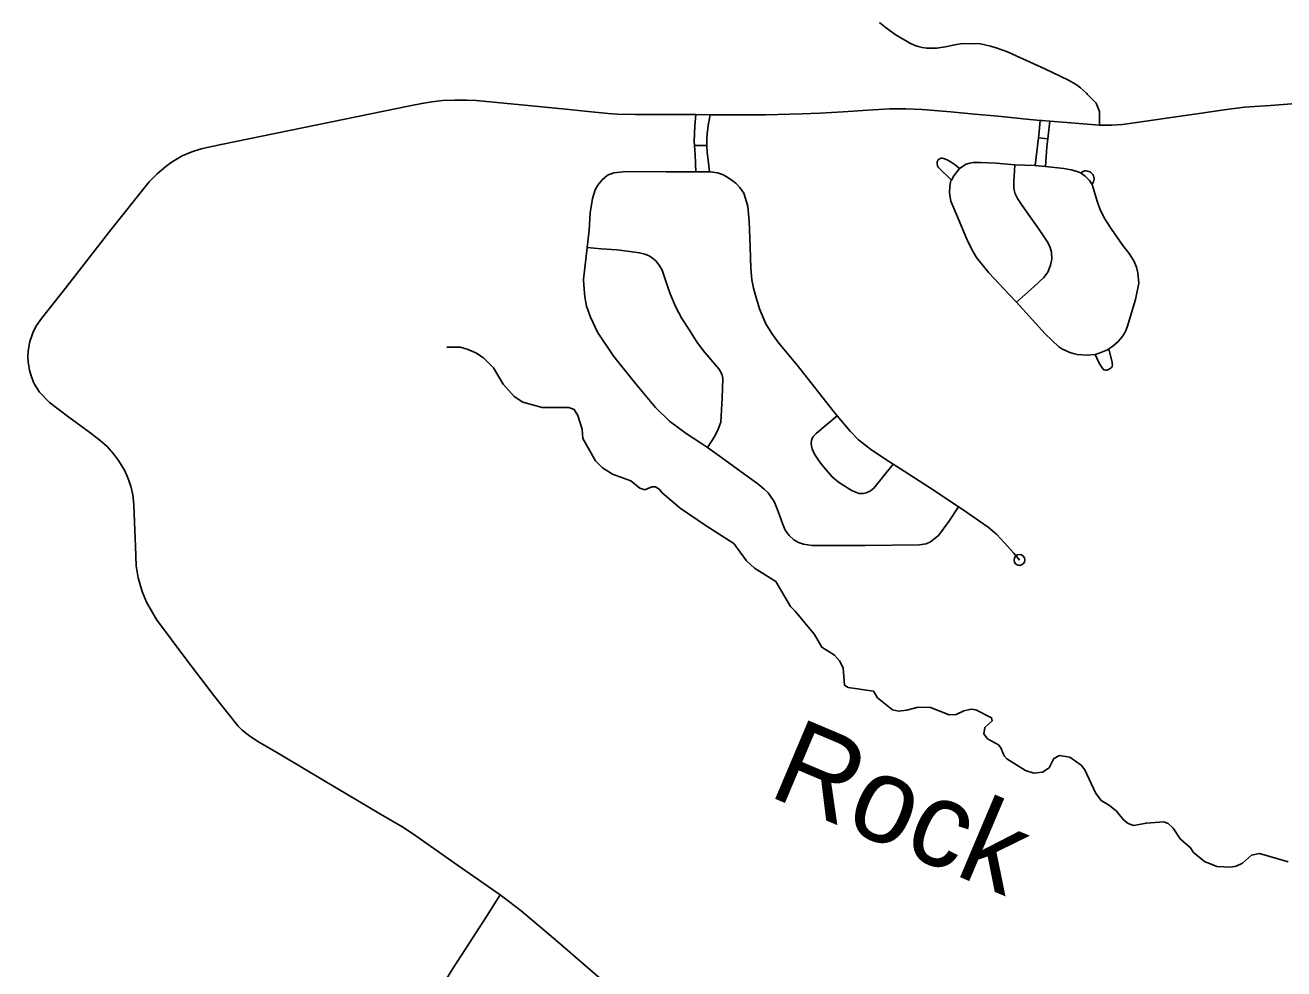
# Model space of a CAD drawing. Extents: x -19 to 366, y -4 to 359.
# Drawn here: x 142.275 to 143.458, y 193.183 to 194.069 of the extents above; entities that cross this region are included whole.
import ezdxf

# ---------------------------------------------------------------- set-up
doc = ezdxf.new("R2010")
doc.units = 0
for name, color, linetype in [('R_ROW Annot', 7, 'Continuous'), ('R_Striping', 7, 'Continuous'), ('R_Survey Control', 7, 'Continuous'), ('R_Temp Easement', 7, 'Continuous'), ('Sheet Fence', 7, 'Continuous')]:
    doc.layers.add(name, color=color, linetype=linetype)

msp = doc.modelspace()

# ---------------------------------------------------------------- linework, layer by layer
at = {"layer": 'R_ROW Annot'}
msp.add_lwpolyline([(143.2733, 194.0043), (143.2725, 194.0053), (143.2699, 194.008), (143.2671, 194.0104), (143.2642, 194.0126), (143.2624, 194.0137), (143.2556, 194.0177), (143.2336, 194.0281), (143.2162, 194.0361), (143.2066, 194.0405), (143.1985, 194.0441), (143.1932, 194.0462), (143.1879, 194.048), (143.1825, 194.0496), (143.177, 194.0508), (143.173, 194.0516), (143.1569, 194.052), (143.1541, 194.0516), (143.1506, 194.0511), (143.1473, 194.0505), (143.1445, 194.0499), (143.1418, 194.0493), (143.1319, 194.0477), (143.1279, 194.0475), (143.1228, 194.0475), (143.1181, 194.0483), (143.1145, 194.0491), (143.1115, 194.0501), (143.1067, 194.0524), (143.104, 194.0539), (143.0959, 194.0585), (143.0929, 194.0604), (143.0857, 194.0658), (143.0834, 194.0675), (143.0782, 194.0717)], dxfattribs=at)
at = {"layer": 'R_Striping'}
for p, q in [((142.9043, 193.9562), (142.9159, 193.9562)), ((143.2276, 193.9633), (143.2364, 193.9625)), ((142.8034, 193.8604), (142.8052, 193.8768)), ((142.8001, 193.8303), (142.8034, 193.8604)), ((143.0189, 193.686), (143.0385, 193.7023)), ((143.0727, 193.6344), (143.091, 193.657))]:
    msp.add_line(p, q, dxfattribs=at)
for points in [[(143.2848, 193.9752), (143.2962, 193.9752), (143.3065, 193.976), (143.3764, 193.9858), (143.4042, 193.99), (143.4212, 193.9921), (143.4455, 193.9938), (143.4694, 193.9957), (143.4884, 193.9971), (143.5084, 193.9987), (143.5217, 194.0017), (143.5469, 194.0079), (143.5711, 194.0132), (143.5843, 194.0154), (143.5968, 194.0164), (143.608, 194.0172), (143.6204, 194.0177), (143.6361, 194.0167), (143.6637, 194.0127), (143.6699, 194.0116)], [(142.8853, 193.9853), (142.8485, 193.9854), (142.8319, 193.9855), (142.8233, 193.9862), (142.8012, 193.9885), (142.7835, 193.9903), (142.7414, 193.9943), (142.6992, 193.9984), (142.6904, 193.9987), (142.6789, 193.9988), (142.6674, 193.9985), (142.6576, 193.9973), (142.648, 193.9957), (142.6368, 193.9933), (142.5498, 193.9755), (142.4595, 193.9572), (142.4406, 193.9532), (142.4319, 193.9503), (142.4229, 193.9464), (142.4136, 193.941), (142.4074, 193.9364), (142.3993, 193.9295), (142.3919, 193.9221), (142.3559, 193.8769), (142.3133, 193.8223), (142.2906, 193.7937), (142.286, 193.7872), (142.2829, 193.7812), (142.2816, 193.7773), (142.2797, 193.772), (142.2787, 193.7672), (142.2782, 193.7626), (142.278, 193.758), (142.2782, 193.7529), (142.2788, 193.749), (142.2795, 193.7453), (142.2811, 193.7397), (142.2836, 193.7329), (142.2888, 193.7246), (142.2981, 193.7148), (142.3163, 193.7011), (142.3361, 193.6865), (142.3459, 193.6792), (142.3524, 193.6733), (142.3584, 193.6667), (142.3631, 193.6604), (142.3686, 193.6513), (142.3719, 193.6441), (142.3746, 193.6362), (142.3766, 193.6281), (142.3774, 193.6191), (142.378, 193.6025), (142.3792, 193.5799), (142.3797, 193.5612), (142.3814, 193.5502), (142.3853, 193.5371), (142.3893, 193.5271), (142.3987, 193.511), (142.4273, 193.4728), (142.4537, 193.4383), (142.4756, 193.4106), (142.4793, 193.407), (142.4865, 193.4013), (142.4945, 193.3961), (142.5156, 193.3838), (142.5575, 193.3588), (142.6092, 193.3282), (142.6309, 193.3154), (142.6423, 193.3076), (142.6817, 193.2803), (142.7216, 193.2522)], [(143.1895, 193.9838), (143.1674, 193.9857), (143.145, 193.9878), (143.1181, 193.9901), (143.103, 193.9907), (143.0878, 193.9905), (143.0671, 193.9895), (143.0439, 193.9878), (143.0222, 193.9867), (143.0055, 193.9858), (142.9711, 193.9849), (142.919, 193.9851)], [(142.9054, 193.9852), (142.8853, 193.9853)], [(142.9043, 193.9562), (142.9041, 193.9601), (142.9046, 193.9746), (142.9054, 193.9852)], [(142.919, 193.9851), (142.9054, 193.9852)], [(142.919, 193.9851), (142.9171, 193.975), (142.9162, 193.9671), (142.916, 193.9621), (142.9159, 193.9562)], [(143.229, 193.9798), (143.2132, 193.9814), (143.1895, 193.9838)], [(143.229, 193.9798), (143.2279, 193.966), (143.2276, 193.9633)], [(143.2381, 193.9791), (143.2311, 193.9796), (143.229, 193.9798)], [(143.2381, 193.9791), (143.2367, 193.9653), (143.2364, 193.9625)], [(143.2849, 193.9752), (143.2542, 193.9778), (143.2381, 193.9791)], [(142.9056, 193.9314), (142.9048, 193.9473), (142.9043, 193.9562)], [(142.9159, 193.9562), (142.9159, 193.9562), (142.9162, 193.95), (142.9179, 193.937), (142.9184, 193.9314)], [(143.2276, 193.9633), (143.2244, 193.9373)], [(143.2364, 193.9625), (143.2355, 193.955), (143.2341, 193.9366)], [(143.1457, 193.9237), (143.1334, 193.9357), (143.1326, 193.9371), (143.1322, 193.9389), (143.1323, 193.9408), (143.1334, 193.9427), (143.1343, 193.9434), (143.1352, 193.944), (143.1361, 193.9442), (143.1371, 193.9442), (143.1391, 193.9437), (143.1418, 193.9428), (143.1456, 193.9405), (143.1493, 193.938), (143.1534, 193.9346)], [(142.8052, 193.8768), (142.8064, 193.8928), (142.8083, 193.9065), (142.811, 193.9145), (142.8135, 193.9188), (142.8174, 193.9238), (142.8227, 193.9282), (142.8285, 193.9305), (142.8373, 193.9314), (142.8542, 193.9319), (142.8777, 193.9314), (142.9056, 193.9314)], [(142.9056, 193.9314), (142.9184, 193.9314)], [(142.9184, 193.9314), (142.9193, 193.9314), (142.9258, 193.9306), (142.9305, 193.9291), (142.9341, 193.9272), (142.9385, 193.9244), (142.9431, 193.9209), (142.947, 193.9168), (142.9505, 193.9113), (142.9532, 193.9033), (142.9545, 193.899), (142.9557, 193.885), (142.9565, 193.8608), (142.9573, 193.8409), (142.9582, 193.83), (142.9597, 193.8223), (142.9618, 193.8143), (142.9653, 193.8027), (142.9713, 193.7887), (142.9769, 193.7795), (142.9836, 193.7706), (143.0012, 193.7496), (143.0343, 193.7074), (143.0385, 193.7023)], [(143.1457, 193.9237), (143.1481, 193.9278), (143.1532, 193.9345), (143.1534, 193.9346)], [(143.1534, 193.9346), (143.1596, 193.9386), (143.1631, 193.9396), (143.1662, 193.9402), (143.1732, 193.9403), (143.1878, 193.9395)], [(143.1878, 193.9395), (143.2054, 193.9381)], [(143.2068, 193.8089), (143.2234, 193.8236), (143.2326, 193.8322), (143.2364, 193.8373), (143.2389, 193.8437), (143.2399, 193.8495), (143.2396, 193.856), (143.2385, 193.8605), (143.2362, 193.8652), (143.2287, 193.8762), (143.2122, 193.8997), (143.2078, 193.9063), (143.2056, 193.9107), (143.2047, 193.9146), (143.2045, 193.9168), (143.2044, 193.922), (143.2054, 193.9381)], [(143.2054, 193.9381), (143.2241, 193.9373), (143.2244, 193.9373)], [(143.2244, 193.9373), (143.2341, 193.9366)], [(143.2341, 193.9366), (143.2514, 193.9345), (143.2581, 193.9333), (143.2639, 193.9317), (143.2669, 193.9304)], [(143.1504, 193.8913), (143.1453, 193.9039), (143.1446, 193.9077), (143.144, 193.912), (143.1442, 193.9181), (143.1453, 193.9232), (143.1457, 193.9237)], [(143.2669, 193.9304), (143.268, 193.9299), (143.2714, 193.9275), (143.2753, 193.9234), (143.2778, 193.9197), (143.2778, 193.9196)], [(143.2778, 193.9196), (143.2799, 193.9132), (143.2826, 193.9039), (143.2855, 193.8957), (143.2899, 193.8872), (143.2914, 193.8847)], [(143.2068, 193.8089), (143.2004, 193.8159), (143.1808, 193.8365), (143.1693, 193.8509), (143.165, 193.8585), (143.1601, 193.8683), (143.1504, 193.8913)], [(143.3219, 193.827), (143.321, 193.8366), (143.3196, 193.8418), (143.317, 193.8478), (143.3127, 193.8546), (143.3069, 193.8624), (143.2961, 193.8777), (143.2914, 193.8847)], [(142.9164, 193.6725), (142.9233, 193.6833), (142.9266, 193.6896), (142.9289, 193.6962), (142.9303, 193.7191), (142.931, 193.7372), (142.9304, 193.7405), (142.9291, 193.7434), (142.9271, 193.7463), (142.914, 193.7617), (142.9068, 193.7711), (142.8995, 193.7827), (142.8924, 193.7938), (142.8867, 193.8044), (142.8815, 193.8168), (142.8789, 193.8241), (142.8765, 193.8315), (142.8739, 193.8391), (142.871, 193.8439), (142.8679, 193.8479), (142.8649, 193.8505), (142.8618, 193.8526), (142.8577, 193.8542), (142.8526, 193.8553), (142.8436, 193.8567), (142.8312, 193.8581), (142.8166, 193.8592), (142.8034, 193.8604)], [(142.8001, 193.8303), (142.8003, 193.8249), (142.8012, 193.8139), (142.8029, 193.8053), (142.8066, 193.7948), (142.8133, 193.7807), (142.8284, 193.7581), (142.8489, 193.7327), (142.8675, 193.7101), (142.8808, 193.6972), (142.8966, 193.6855), (142.911, 193.6763), (142.9164, 193.6725)], [(143.3219, 193.827), (143.3187, 193.8115), (143.3108, 193.7854), (143.309, 193.7809), (143.3061, 193.7766), (143.3024, 193.7722), (143.2975, 193.7677), (143.2936, 193.7651)], [(143.2466, 193.7672), (143.2338, 193.7793), (143.2216, 193.7927), (143.2068, 193.8089)], [(143.2808, 193.76), (143.2807, 193.76), (143.273, 193.7592), (143.2637, 193.7599), (143.2601, 193.7608), (143.257, 193.7617), (143.2496, 193.7651), (143.2466, 193.7672)], [(143.2936, 193.7651), (143.2923, 193.7642), (143.2844, 193.7611), (143.2808, 193.76)], [(143.2808, 193.76), (143.2846, 193.7518), (143.2873, 193.7474), (143.2885, 193.7459), (143.2892, 193.7456), (143.2906, 193.7452), (143.2918, 193.7452), (143.294, 193.746), (143.2957, 193.7472), (143.2966, 193.7485), (143.2969, 193.7497), (143.2968, 193.7514), (143.2966, 193.7523), (143.2936, 193.7651)], [(143.0385, 193.7023), (143.0505, 193.6878), (143.0585, 193.6797), (143.0696, 193.6709), (143.0831, 193.662), (143.091, 193.657)], [(143.0189, 193.686), (143.0159, 193.6828), (143.015, 193.6811), (143.0143, 193.6792), (143.014, 193.6766), (143.0141, 193.6739), (143.0147, 193.6713), (143.0157, 193.6692), (143.0171, 193.6662), (143.0194, 193.6625), (143.023, 193.6575), (143.0279, 193.6516), (143.0337, 193.6451), (143.0397, 193.6399), (143.0456, 193.6361), (143.0515, 193.6324), (143.0556, 193.6305), (143.0591, 193.6293), (143.0605, 193.6292), (143.0618, 193.6292), (143.0632, 193.6294), (143.0656, 193.63), (143.0696, 193.6319), (143.0727, 193.6344)], [(142.9164, 193.6725), (142.9274, 193.6648), (142.9539, 193.6456), (142.9637, 193.6384), (142.9697, 193.6335), (142.9734, 193.6298), (142.9792, 193.6217), (142.9821, 193.615), (142.9843, 193.6088), (142.987, 193.601), (142.9896, 193.595), (142.9933, 193.5898), (142.9976, 193.5858), (143.0019, 193.5832), (143.0068, 193.5816), (143.0148, 193.5805), (143.0307, 193.5803), (143.0647, 193.5806), (143.1158, 193.5812), (143.1221, 193.5821), (143.126, 193.5839), (143.1336, 193.5897), (143.1434, 193.603), (143.1523, 193.6168)], [(143.091, 193.657), (143.1014, 193.6504), (143.1296, 193.632), (143.1523, 193.6168)], [(143.1523, 193.6168), (143.1566, 193.614), (143.1802, 193.5978)], [(143.2097, 193.5668), (143.2043, 193.5731), (143.1954, 193.5833), (143.1883, 193.5907), (143.1802, 193.5978)], [(142.6048, 193.0965), (142.609, 193.103), (142.6124, 193.1081), (142.6163, 193.1142), (142.6192, 193.1185), (142.6246, 193.124), (142.6429, 193.141), (142.6552, 193.1521), (142.662, 193.1591), (142.6664, 193.1646), (142.6729, 193.176), (142.6771, 193.1831), (142.6895, 193.202), (142.7087, 193.2319), (142.7216, 193.2522)], [(142.7216, 193.2522), (142.7242, 193.2504), (142.7414, 193.2374), (142.776, 193.2082), (142.8037, 193.184), (142.8313, 193.1601)]]:
    msp.add_lwpolyline(points, dxfattribs=at)
msp.add_circle((143.2096, 193.5669), 0.00509, dxfattribs=at)
msp.add_arc((143.2721, 193.9247), 0.00765, 318.0474, 132.7124, dxfattribs=at)
at = {"layer": 'R_Survey Control'}
msp.add_lwpolyline([(143.2848, 193.9752), (143.2848, 193.988), (143.2818, 193.9959), (143.2733, 194.0043)], dxfattribs=at)
at = {"layer": 'R_Temp Easement'}
for points in [[(142.8677, 193.6356), (142.8643, 193.6356), (142.8575, 193.6327), (142.8529, 193.6342), (142.8445, 193.6411), (142.8274, 193.6476), (142.8179, 193.6534), (142.8114, 193.66), (142.7993, 193.6811), (142.7986, 193.6896), (142.7947, 193.7027), (142.7913, 193.7082), (142.7863, 193.71), (142.7611, 193.71), (142.7429, 193.7152), (142.7347, 193.7204), (142.7244, 193.7321), (142.7155, 193.7474), (142.706, 193.7568), (142.6989, 193.7615), (142.6907, 193.765), (142.6841, 193.7666), (142.6716, 193.7667)], [(143.3074, 193.3226), (143.3008, 193.331), (143.2943, 193.3363), (143.2863, 193.3408), (143.2812, 193.3481), (143.2711, 193.3697), (143.2675, 193.3742), (143.257, 193.3815), (143.2473, 193.3831), (143.242, 193.3804), (143.2374, 193.3715), (143.2312, 193.3676), (143.2232, 193.3666), (143.2154, 193.369), (143.1979, 193.3799), (143.1954, 193.3829), (143.1921, 193.3904), (143.1898, 193.3933), (143.1795, 193.3989), (143.1763, 193.4036), (143.177, 193.4095), (143.1839, 193.4156), (143.1834, 193.4186), (143.1687, 193.4261), (143.1641, 193.4268), (143.1573, 193.425), (143.1502, 193.4218), (143.1435, 193.4213), (143.1262, 193.4284), (143.1145, 193.4287), (143.1039, 193.4259), (143.096, 193.4249), (143.0904, 193.426), (143.0763, 193.4375), (143.0725, 193.4435), (143.0488, 193.4469), (143.0453, 193.4491), (143.0439, 193.4654), (143.0406, 193.4722), (143.0358, 193.4773), (143.024, 193.4848), (143.0169, 193.4969), (142.9989, 193.5187), (142.9945, 193.5233), (142.9806, 193.5465), (142.9606, 193.559), (142.9532, 193.5661), (142.9411, 193.5822), (142.9154, 193.5988), (142.8908, 193.6155), (142.874, 193.63), (142.8711, 193.6334), (142.8677, 193.6356)], [(143.4621, 193.2833), (143.4351, 193.291), (143.4278, 193.2896), (143.4191, 193.2821), (143.4131, 193.2791), (143.4083, 193.2783), (143.3951, 193.2789), (143.3835, 193.2837), (143.3732, 193.2922), (143.3703, 193.2963), (143.3607, 193.305), (143.3542, 193.3148), (143.3493, 193.3193), (143.3453, 193.321), (143.329, 193.3197), (143.3167, 193.3175), (143.3117, 193.3192), (143.3074, 193.3226)]]:
    msp.add_lwpolyline(points, dxfattribs=at)
at = {"layer": 'Sheet Fence'}
for points in [[(146.7783, 1.697), (146.5788, 10.3131), (146.3785, 18.9294), (146.1776, 27.5458), (145.9759, 36.1624), (145.7736, 44.7791), (145.5705, 53.396), (145.3668, 62.013), (145.1624, 70.6301), (144.9572, 79.2474), (144.7514, 87.8648), (144.5449, 96.4823), (144.3377, 105.1), (144.1299, 113.7179), (143.9213, 122.3359), (143.712, 130.954), (143.5021, 139.5723), (143.2915, 148.1907), (143.0802, 156.8092), (142.8682, 165.4279), (142.6555, 174.0468), (142.4422, 182.6658), (142.2282, 191.2849), (142.0135, 199.9042), (141.7981, 208.5236), (141.582, 217.1432), (141.3653, 225.7629), (141.1479, 234.3828), (140.9298, 243.0028), (140.711, 251.623), (140.4916, 260.2433), (140.2715, 268.8638), (140.0508, 277.4844), (139.8293, 286.1051), (139.6072, 294.726), (139.3845, 303.3471), (139.161, 311.9683), (138.937, 320.5896), (138.7122, 329.2111), (138.4868, 337.8328), (138.2607, 346.4546)], [(0, 189.5162), (7.1121, 189.5206), (14.2243, 189.5339), (21.3364, 189.556), (28.4484, 189.5869), (35.5605, 189.6267), (42.6725, 189.6754), (49.7844, 189.7329), (56.8962, 189.7992), (64.0079, 189.8744), (71.1196, 189.9584), (78.2311, 190.0512), (85.3425, 190.1529), (92.4538, 190.2635), (99.5649, 190.3829), (106.6759, 190.5111), (113.7867, 190.6482), (120.8974, 190.7941), (128.0078, 190.9489), (135.1181, 191.1125), (142.2282, 191.2849), (149.338, 191.4662), (156.4476, 191.6563), (163.5569, 191.8553), (170.666, 192.0631), (177.7749, 192.2798), (184.8835, 192.5053), (191.9917, 192.7396), (199.0997, 192.9828), (206.2074, 193.2348), (213.3147, 193.4956), (220.4218, 193.7653), (227.5285, 194.0438), (234.6348, 194.3312), (241.7408, 194.6274), (248.8464, 194.9324), (255.9516, 195.2463), (263.0564, 195.569), (270.1608, 195.9005), (277.2648, 196.2409), (284.3683, 196.5901), (291.4715, 196.9481), (298.5741, 197.315), (305.6763, 197.6907), (312.7781, 198.0753), (319.8793, 198.4686), (326.9801, 198.8708), (334.0804, 199.2818), (341.1801, 199.7017)]]:
    msp.add_spline(points, degree=3, dxfattribs=at)

# ---------------------------------------------------------------- texts
at = {"layer": 'R_Temp Easement'}
msp.add_text('Rock', height=0.08, rotation=337.0448, dxfattribs=at).set_placement((142.972, 193.3459))

doc.saveas('drawing.dxf')
